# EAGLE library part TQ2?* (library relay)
LOW PROFILE 2 FORM C RELAY NAiS Source: http://www.mew-europe.com/.. en_ds_61020_0001.pdf Source: http://www.mew-europe.com/.. en_ds_61020_0004.pdf
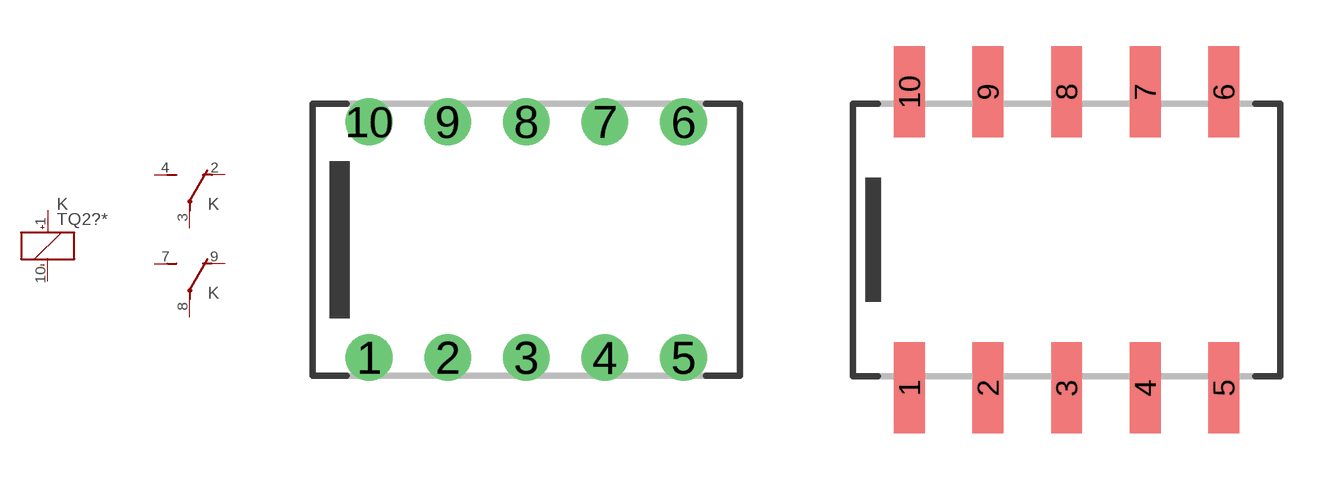
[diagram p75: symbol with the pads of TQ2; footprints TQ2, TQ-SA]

Designator prefix K; gates _=K+- 1=U 2=U

## TQ2-3V (MF: AROMAT/ MATSUSHITA; MPN: TQ2-3V; OC_FARNELL: 1703746; OC_NEWARK: 73K2455), TQ2-4.5V (MF: AROMAT/ MATSUSHITA; MPN: TQ2-4.5V; OC_FARNELL: 1163566; OC_NEWARK: 64K3199), TQ2-5V (MF: AROMAT/ MATSUSHITA; MPN: TQ2-5V; OC_FARNELL: 1175716; OC_NEWARK: 64K3200), TQ2-6V (MF: AROMAT/ MATSUSHITA; MPN: TQ2-6V; OC_FARNELL: unknown; OC_NEWARK: 64K3201), TQ2-9V (MPN: TQ2-9V; OC_FARNELL: unknown; OC_NEWARK: 13P9201), TQ2-12V (MF: AROMAT/ MATSUSHITA; MPN: TQ2-12V; OC_FARNELL: 1200949; OC_NEWARK: 64K3197), TQ2-24V (MF: AROMAT/ MATSUSHITA; MPN: TQ2-24V; OC_FARNELL: 1175717; OC_NEWARK: 64K3198), TQ2-48V (MPN: TQ2-48V; OC_FARNELL: unknown; OC_NEWARK: 13P9197)  [TQ2]
1  _:+  pas
2  1:O  pas
3  1:P  pas
4  1:S  pas
7  2:S  pas
8  2:P  pas
9  2:O  pas
10  _:-  pas

## TQ2-L-3V (MF: AROMAT/ MATSUSHITA; MPN: TQ2-L-3V; OC_FARNELL: unknown; OC_NEWARK: 87F3168), TQ2-L-4.5V (MPN: TQ2-L-4.5V; OC_FARNELL: unknown; OC_NEWARK: 15P9767), TQ2-L-5V (MF: AROMAT/ MATSUSHITA; MPN: TQ2-L-5V; OC_FARNELL: 1448361; OC_NEWARK: 64K3191), TQ2-L-6V (OC_FARNELL: unknown; OC_NEWARK: unknown), TQ2-L-9V (OC_FARNELL: unknown; OC_NEWARK: unknown), TQ2-L-12V (MF: AROMAT/ MATSUSHITA; MPN: TQ2-L-12V; OC_FARNELL: unknown; OC_NEWARK: 64K3190), TQ2-L-24V (OC_FARNELL: unknown; OC_NEWARK: unknown)  [TQ2]
1  _:-  pas
2  1:O  pas
3  1:P  pas
4  1:S  pas
7  2:S  pas
8  2:P  pas
9  2:O  pas
10  _:+  pas

## TQ2-SA-1.5V (MPN: TQ2SA-1.5V-Z; OC_FARNELL: unknown; OC_NEWARK: 13P9205), TQ2-SA-3V (MPN: TQ2SA-3V; OC_FARNELL: unknown; OC_NEWARK: 10C9847), TQ2-SA-4.5V (MPN: TQ2SA-4.5V; OC_FARNELL: unknown; OC_NEWARK: 92B3979), TQ2-SA-5V (MF: AROMAT/ MATSUSHITA; MPN: TQ2SA-5V; OC_FARNELL: 1124054; OC_NEWARK: 64K3205), TQ2-SA-6V (MPN: TQ2SA-6V; OC_FARNELL: unknown; OC_NEWARK: 13P9219), TQ2-SA-9V (MPN: TQ2SA-9V; OC_FARNELL: unknown; OC_NEWARK: 13P9220), TQ2-SA-12V (MF: AROMAT/ MATSUSHITA; MPN: TQ2SA-12V; OC_FARNELL: 1124056; OC_NEWARK: 64K3203), TQ2-SA-24V (MPN: TQ2SA-24V; OC_FARNELL: unknown; OC_NEWARK: 13P9208), TQ2-SA-48V (MPN: TQ2SA-48V; OC_FARNELL: unknown; OC_NEWARK: 13P9215)  [TQ-SA]
Pads as for TQ2

## TQ2SA-L-1.5V (OC_FARNELL: unknown; OC_NEWARK: unknown), TQ2SA-L-3V (MPN: TQ2SA-L-3V; OC_FARNELL: unknown; OC_NEWARK: 15P9778), TQ2SA-L-4.5V (MPN: TQ2SA-L-4.5V; OC_FARNELL: unknown; OC_NEWARK: 15P9779), TQ2SA-L-5V (MPN: TQ2SA-L-5V; OC_FARNELL: unknown; OC_NEWARK: 15P9780), TQ2SA-L-6V (OC_FARNELL: unknown; OC_NEWARK: unknown), TQ2SA-L-9V (OC_FARNELL: unknown; OC_NEWARK: unknown), TQ2SA-L-12V (MPN: TQ2SA-L-12V; OC_FARNELL: unknown; OC_NEWARK: 15P9777), TQ2SA-L-24V (OC_FARNELL: unknown; OC_NEWARK: unknown)  [TQ-SA]
Pads as for TQ2

## TQ2-SL-1.5V (OC_FARNELL: unknown; OC_NEWARK: unknown), TQ2-SL-3V (MPN: TQ2SL-3V; OC_FARNELL: unknown; OC_NEWARK: 13P9226), TQ2-SL-4.5V (OC_FARNELL: unknown; OC_NEWARK: unknown), TQ2-SL-5V (MPN: TQ2SL-5V; OC_FARNELL: unknown; OC_NEWARK: 13P9228), TQ2-SL-6V (OC_FARNELL: unknown; OC_NEWARK: unknown), TQ2-SL-9V (OC_FARNELL: unknown; OC_NEWARK: unknown), TQ2-SL-12V (MPN: TQ2SL-12V; OC_FARNELL: unknown; OC_NEWARK: 13P9222), TQ2-SL-24V (MPN: TQ2SL-24V; OC_FARNELL: unknown; OC_NEWARK: 13P9224)  [TQ-SL]
Pads as for TQ2

## TQ2SL-L-1.5V (OC_FARNELL: unknown; OC_NEWARK: unknown), TQ2SL-L-3V (MPN: TQ2SL-L-3V; OC_FARNELL: unknown; OC_NEWARK: 15P9793), TQ2SL-L-4.5V (OC_FARNELL: unknown; OC_NEWARK: unknown), TQ2SL-L-5V (OC_FARNELL: unknown; OC_NEWARK: unknown), TQ2SL-L-6V (OC_FARNELL: unknown; OC_NEWARK: unknown), TQ2SL-L-9V (OC_FARNELL: unknown; OC_NEWARK: unknown), TQ2SL-L-12V (OC_FARNELL: unknown; OC_NEWARK: unknown), TQ2SL-L-24V (MF: AROMAT/ MATSUSHITA; MPN: TQ2SL-L-24V; OC_FARNELL: unknown; OC_NEWARK: 10C9870)  [TQ-SL]
Pads as for TQ2

## TQ2-SS-1.5V (MPN: TQ2SS-1.5V; OC_FARNELL: unknown; OC_NEWARK: 13P9230), TQ2-SS-3V (MF: AROMAT/ MATSUSHITA; MPN: TQ2SS-3V; OC_FARNELL: unknown; OC_NEWARK: 10C9995), TQ2-SS-4.5V (MPN: TQ2SS-4.5V; OC_FARNELL: unknown; OC_NEWARK: 13P9234), TQ2-SS-5V (MF: AROMAT/ MATSUSHITA; MPN: TQ2SS-5V; OC_FARNELL: unknown; OC_NEWARK: 11C0005), TQ2-SS-6V (OC_FARNELL: unknown; OC_NEWARK: unknown), TQ2-SS-9V (OC_FARNELL: unknown; OC_NEWARK: unknown), TQ2-SS-12V (MPN: TQ2SS-12V; OC_FARNELL: unknown; OC_NEWARK: 13P9231), TQ2-SS-24V (MPN: TQ2SS-24V-Z; OC_FARNELL: unknown; OC_NEWARK: 13P9232), TQ2-SS-48V (MF: AROMAT/ MATSUSHITA; MPN: TQ2SS-48V; OC_FARNELL: unknown; OC_NEWARK: 11C0002)  [TQ-SS]
Pads as for TQ2

## TQ2SS-L-1.5V (OC_FARNELL: unknown; OC_NEWARK: unknown), TQ2SS-L-3V (OC_FARNELL: unknown; OC_NEWARK: unknown), TQ2SS-L-4.5V (MF: AROMAT/ MATSUSHITA; MPN: TQ2SS-L-4.5V; OC_FARNELL: unknown; OC_NEWARK: 10C9950), TQ2SS-L-5V (MPN: TQ2SS-L-5V; OC_FARNELL: unknown; OC_NEWARK: 15P9797), TQ2SS-L-6V (OC_FARNELL: unknown; OC_NEWARK: unknown), TQ2SS-L-9V (OC_FARNELL: unknown; OC_NEWARK: unknown), TQ2SS-L-12V (OC_FARNELL: unknown; OC_NEWARK: unknown), TQ2SS-L-24V (OC_FARNELL: unknown; OC_NEWARK: unknown)  [TQ-SS]
Pads as for TQ2

## Footprint TQ2 (pad centres in mm)
LOW PROFILE 2 FORM C RELAY NAiS Source: http://www.mew-europe.com/.. en_ds_61020_0001.pdf
drill 1 round: 1 -5.08,-3.81; 2 -2.54,-3.81; 3 0,-3.81; 4 2.54,-3.81; 5 5.08,-3.81; 6 5.08,3.81; 7 2.54,3.81; 8 0,3.81; 9 -2.54,3.81; 10 -5.08,3.81

## Footprint TQ-SA (pad centres in mm)
LOW-PROFILE TQ-SMD RELAYS NAiS Source: http://www.mew-europe.com/.. en_ds_61021_0004.pdf
smd 1 x 2.94: 1 -5.08,-4.78; 2 -2.54,-4.78; 3 0,-4.78; 4 2.54,-4.78; 5 5.08,-4.78; 6 5.08,4.78; 7 2.54,4.78; 8 0,4.78; 9 -2.54,4.78; 10 -5.08,4.78

## Footprint TQ-SL (pad centres in mm)
LOW-PROFILE TQ-SMD RELAYS NAiS Source: http://www.mew-europe.com/.. en_ds_61021_0004.pdf
smd 1 x 2.94: 1 -5.08,-4.78; 2 -2.54,-4.78; 3 0,-4.78; 4 2.54,-4.78; 5 5.08,-4.78; 6 5.08,4.78; 7 2.54,4.78; 8 0,4.78; 9 -2.54,4.78; 10 -5.08,4.78

## Footprint TQ-SS (pad centres in mm)
LOW-PROFILE TQ-SMD RELAYS NAiS Source: http://www.mew-europe.com/.. en_ds_61021_0004.pdf
smd 1 x 1.84: 1 -5.08,-4.23; 2 -2.54,-4.23; 3 0,-4.23; 4 2.54,-4.23; 5 5.08,-4.23; 6 5.08,4.23; 7 2.54,4.23; 8 0,4.23; 9 -2.54,4.23; 10 -5.08,4.23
